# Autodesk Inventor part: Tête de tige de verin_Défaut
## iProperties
Shininess: 64.0
Length Units: 11269
Angle Units: 11279
Time Units: 11290
Mass Units: 11283
Length Display Precision: 3
Angle Display Precision: 2
Compacted: True
Part Number: Tête de tige de verin_Défaut
Document SubType Name: Modeling
Created: 2006-11
Material: Par défaut
Designer: profs_sti
Density: 0.0
Volumn: 0.0
Area: 0.0
PropertySet Name: Model Information
Control State: 0
Master: False
Checked Out: False
Author: profs_sti
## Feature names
1. Base1
